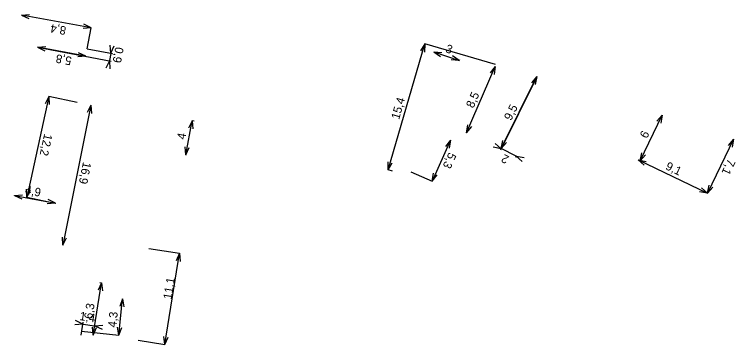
# Model space of a CAD drawing. Extents: x -740739.3 to -740654, y -1040294.6 to -1040255.5.
import ezdxf

# ---------------------------------------------------------------- set-up
doc = ezdxf.new("R2010")
doc.units = 0
doc.layers.add('Kota_VN', color=7, linetype='Continuous')

msp = doc.modelspace()

# ---------------------------------------------------------------- linework, layer by layer
at = {"layer": 'Kota_VN'}
for p, q in [((-740738.51, -1040255.62), (-740737.553, -1040255.542)), ((-740738.51, -1040255.62), (-740738.51, -1040255.62)), ((-740730.261, -1040257.116), (-740738.51, -1040255.62)), ((-740738.51, -1040255.62), (-740737.641, -1040256.031)), ((-740730.261, -1040257.116), (-740731.218, -1040257.194)), ((-740730.261, -1040257.116), (-740731.13, -1040256.705)), ((-740730.71, -1040259.59), (-740730.261, -1040257.116)), ((-740727.938, -1040260.117), (-740728.011, -1040259.159)), ((-740695.131, -1040273.914), (-740690.783, -1040259.027)), ((-740690.783, -1040259.027), (-740691.282, -1040259.848)), ((-740690.783, -1040259.027), (-740690.805, -1040259.987)), ((-740682.416, -1040261.471), (-740690.783, -1040259.027)), ((-740736.59, -1040259.419), (-740735.632, -1040259.345)), ((-740736.59, -1040259.423), (-740736.59, -1040259.419)), ((-740730.877, -1040260.481), (-740736.59, -1040259.419)), ((-740736.59, -1040259.419), (-740735.723, -1040259.833)), ((-740736.59, -1040259.42), (-740727.909, -1040261.048)), ((-740730.711, -1040259.597), (-740727.741, -1040260.154)), ((-740727.901, -1040259.921), (-740728.142, -1040261.207)), ((-740727.938, -1040260.117), (-740727.522, -1040259.251)), ((-740689.72, -1040259.946), (-740689.727, -1040259.968)), ((-740689.727, -1040259.968), (-740686.701, -1040260.976)), ((-740689.727, -1040259.968), (-740688.768, -1040260.026)), ((-740689.727, -1040259.968), (-740688.925, -1040260.498)), ((-740730.877, -1040260.481), (-740731.835, -1040260.555)), ((-740730.877, -1040260.481), (-740731.744, -1040260.067)), ((-740730.879, -1040260.491), (-740730.877, -1040260.481)), ((-740686.701, -1040260.976), (-740687.503, -1040260.446)), ((-740686.678, -1040260.907), (-740686.701, -1040260.976)), ((-740728.105, -1040261.011), (-740728.521, -1040261.877)), ((-740728.105, -1040261.011), (-740728.032, -1040261.969)), ((-740686.701, -1040260.976), (-740687.66, -1040260.918)), ((-740685.831, -1040269.548), (-740682.455, -1040261.702)), ((-740682.455, -1040261.702), (-740683.05, -1040262.456)), ((-740682.455, -1040261.702), (-740682.594, -1040262.652)), ((-740682.444, -1040261.707), (-740682.455, -1040261.702)), ((-740677.534, -1040262.904), (-740681.826, -1040271.593)), ((-740681.734, -1040271.403), (-740677.522, -1040262.897)), ((-740677.522, -1040262.897), (-740678.157, -1040263.618)), ((-740677.522, -1040262.897), (-740677.712, -1040263.839)), ((-740677.53, -1040262.893), (-740677.522, -1040262.897)), ((-740735.251, -1040265.238), (-740737.866, -1040277.168)), ((-740735.251, -1040265.238), (-740735.693, -1040266.091)), ((-740731.91, -1040265.97), (-740735.251, -1040265.238)), ((-740735.251, -1040265.238), (-740735.207, -1040266.198)), ((-740730.29, -1040266.277), (-740733.593, -1040282.829)), ((-740730.29, -1040266.277), (-740730.716, -1040267.138)), ((-740730.3, -1040266.275), (-740730.29, -1040266.277)), ((-740730.29, -1040266.277), (-740730.228, -1040267.236)), ((-740665.297, -1040272.862), (-740662.689, -1040267.436)), ((-740662.689, -1040267.436), (-740663.316, -1040268.164)), ((-740662.689, -1040267.436), (-740662.868, -1040268.38)), ((-740662.687, -1040267.437), (-740662.689, -1040267.436)), ((-740719.062, -1040272.145), (-740718.321, -1040268.102)), ((-740718.321, -1040268.102), (-740718.733, -1040268.97)), ((-740718.088, -1040268.144), (-740718.321, -1040268.102)), ((-740718.321, -1040268.102), (-740718.244, -1040269.06)), ((-740685.831, -1040269.548), (-740685.692, -1040268.598)), ((-740685.831, -1040269.548), (-740685.236, -1040268.794)), ((-740685.822, -1040269.552), (-740685.831, -1040269.548)), ((-740654.26, -1040270.29), (-740657.332, -1040276.68)), ((-740654.25, -1040270.294), (-740657.322, -1040276.685)), ((-740654.25, -1040270.294), (-740654.876, -1040271.023)), ((-740654.25, -1040270.294), (-740654.429, -1040271.238)), ((-740654.259, -1040270.29), (-740654.25, -1040270.294)), ((-740687.741, -1040270.394), (-740689.919, -1040275.26)), ((-740687.741, -1040270.394), (-740688.347, -1040271.139)), ((-740687.741, -1040270.394), (-740687.894, -1040271.342)), ((-740687.75, -1040270.39), (-740687.741, -1040270.394)), ((-740681.737, -1040271.413), (-740682.459, -1040270.779)), ((-740681.734, -1040271.403), (-740681.544, -1040270.461)), ((-740681.734, -1040271.403), (-740681.099, -1040270.682)), ((-740719.062, -1040272.145), (-740719.139, -1040271.187)), ((-740719.062, -1040272.145), (-740718.65, -1040271.277)), ((-740681.737, -1040271.413), (-740682.679, -1040271.224)), ((-740679.799, -1040272.371), (-740681.916, -1040271.325)), ((-740681.743, -1040271.399), (-740681.734, -1040271.403)), ((-740665.297, -1040272.862), (-740665.118, -1040271.918)), ((-740718.98, -1040272.16), (-740719.062, -1040272.145)), ((-740679.974, -1040272.273), (-740680.067, -1040272.462)), ((-740679.978, -1040272.282), (-740679.036, -1040272.471)), ((-740679.978, -1040272.282), (-740679.256, -1040272.916)), ((-740665.55, -1040272.74), (-740665.297, -1040272.862)), ((-740665.544, -1040272.744), (-740665.54, -1040272.735)), ((-740665.54, -1040272.735), (-740657.332, -1040276.68)), ((-740665.54, -1040272.735), (-740664.596, -1040272.914)), ((-740665.54, -1040272.735), (-740664.811, -1040273.361)), ((-740665.297, -1040272.862), (-740664.67, -1040272.134)), ((-740695.131, -1040273.914), (-740695.109, -1040272.954)), ((-740695.131, -1040273.914), (-740694.632, -1040273.093)), ((-740694.594, -1040274.07), (-740695.131, -1040273.914)), ((-740692.42, -1040274.14), (-740689.919, -1040275.26)), ((-740689.919, -1040275.26), (-740689.766, -1040274.312)), ((-740689.919, -1040275.26), (-740689.313, -1040274.515)), ((-740737.866, -1040277.168), (-740737.91, -1040276.208)), ((-740657.332, -1040276.68), (-740658.061, -1040276.054)), ((-740657.322, -1040276.685), (-740657.143, -1040275.741)), ((-740657.322, -1040276.685), (-740656.696, -1040275.956)), ((-740739.336, -1040276.987), (-740739.326, -1040276.936)), ((-740739.326, -1040276.936), (-740738.368, -1040276.865)), ((-740739.326, -1040276.936), (-740734.485, -1040277.854)), ((-740739.326, -1040276.936), (-740738.461, -1040277.354)), ((-740737.866, -1040277.168), (-740737.424, -1040276.315)), ((-740657.332, -1040276.68), (-740658.276, -1040276.501)), ((-740657.326, -1040276.682), (-740657.322, -1040276.685)), ((-740734.502, -1040277.906), (-740737.866, -1040277.168)), ((-740734.485, -1040277.854), (-740735.443, -1040277.925)), ((-740734.485, -1040277.854), (-740735.35, -1040277.436)), ((-740734.495, -1040277.905), (-740734.485, -1040277.854)), ((-740733.593, -1040282.829), (-740733.655, -1040281.87)), ((-740733.593, -1040282.829), (-740733.167, -1040281.968)), ((-740733.622, -1040282.823), (-740733.593, -1040282.829)), ((-740723.423, -1040283.194), (-740719.807, -1040283.777)), ((-740721.543, -1040294.566), (-740719.807, -1040283.777)), ((-740719.807, -1040283.777), (-740720.2, -1040284.654)), ((-740719.807, -1040283.777), (-740719.71, -1040284.733)), ((-740730.005, -1040293.446), (-740729.037, -1040287.258)), ((-740729.037, -1040287.258), (-740729.426, -1040288.136)), ((-740729.221, -1040287.229), (-740729.037, -1040287.258)), ((-740729.037, -1040287.258), (-740728.935, -1040288.213)), ((-740726.983, -1040293.448), (-740726.53, -1040289.17)), ((-740726.53, -1040289.17), (-740726.875, -1040290.067)), ((-740726.53, -1040289.17), (-740726.53, -1040289.17)), ((-740726.53, -1040289.17), (-740726.381, -1040290.119)), ((-740731.234, -1040292.136), (-740732.19, -1040292.229)), ((-740731.234, -1040292.136), (-740732.109, -1040291.739)), ((-740731.45, -1040293.44), (-740731.202, -1040291.938)), ((-740731.432, -1040292.103), (-740729.642, -1040292.399)), ((-740729.978, -1040293.209), (-740729.806, -1040292.169)), ((-740729.839, -1040292.367), (-740728.883, -1040292.274)), ((-740729.839, -1040292.367), (-740728.964, -1040292.764)), ((-740731.413, -1040292.979), (-740726.983, -1040293.448)), ((-740730.005, -1040293.446), (-740730.107, -1040292.491)), ((-740730.005, -1040293.446), (-740729.616, -1040292.568)), ((-740726.983, -1040293.448), (-740727.132, -1040292.499)), ((-740726.983, -1040293.448), (-740726.638, -1040292.551)), ((-740729.967, -1040293.452), (-740730.005, -1040293.446)), ((-740724.68, -1040294.062), (-740721.543, -1040294.566)), ((-740721.543, -1040294.566), (-740721.64, -1040293.61)), ((-740721.543, -1040294.566), (-740721.15, -1040293.689))]:
    msp.add_line(p, q, dxfattribs=at)

# ---------------------------------------------------------------- texts
for s, rotation, p in [('8,4', 169.71882, (-740733.152, -1040256.999)), ('3', 341.56504, (-740688.405, -1040259.987)), ('0,9', 259.3807, (-740727.383, -1040259.334)), ('5,8', 169.47222, (-740732.503, -1040260.585)), ('8,5', 66.71972, (-740685.035, -1040266.686)), ('15,4', 73.72019, (-740693.828, -1040268.025)), ('9,5', 63.65793, (-740680.575, -1040268.162)), ('6', 64.32057, (-740664.498, -1040270.278)), ('12,2', 257.63496, (-740735.796, -1040269.593)), ('4', 79.60967, (-740719.145, -1040270.38)), ('5,3', 245.88582, (-740687.923, -1040271.779)), ('2', 153.71308, (-740680.735, -1040272.354)), ('7,1', 244.32752, (-740654.886, -1040272.542)), ('16,9', 258.71451, (-740731.21, -1040272.928)), ('9,1', 334.32754, (-740662.383, -1040273.808)), ('4,9', 349.25909, (-740738.135, -1040276.755)), ('11,1', 80.85565, (-740720.755, -1040289.278)), ('6,3', 81.11227, (-740730.121, -1040291.601)), ('1,4', 350.60397, (-740731.695, -1040291.654)), ('4,3', 83.95388, (-740727.294, -1040292.586))]:
    msp.add_text(s, height=1, rotation=rotation, dxfattribs=at).set_placement(p)

doc.saveas('drawing.dxf')
